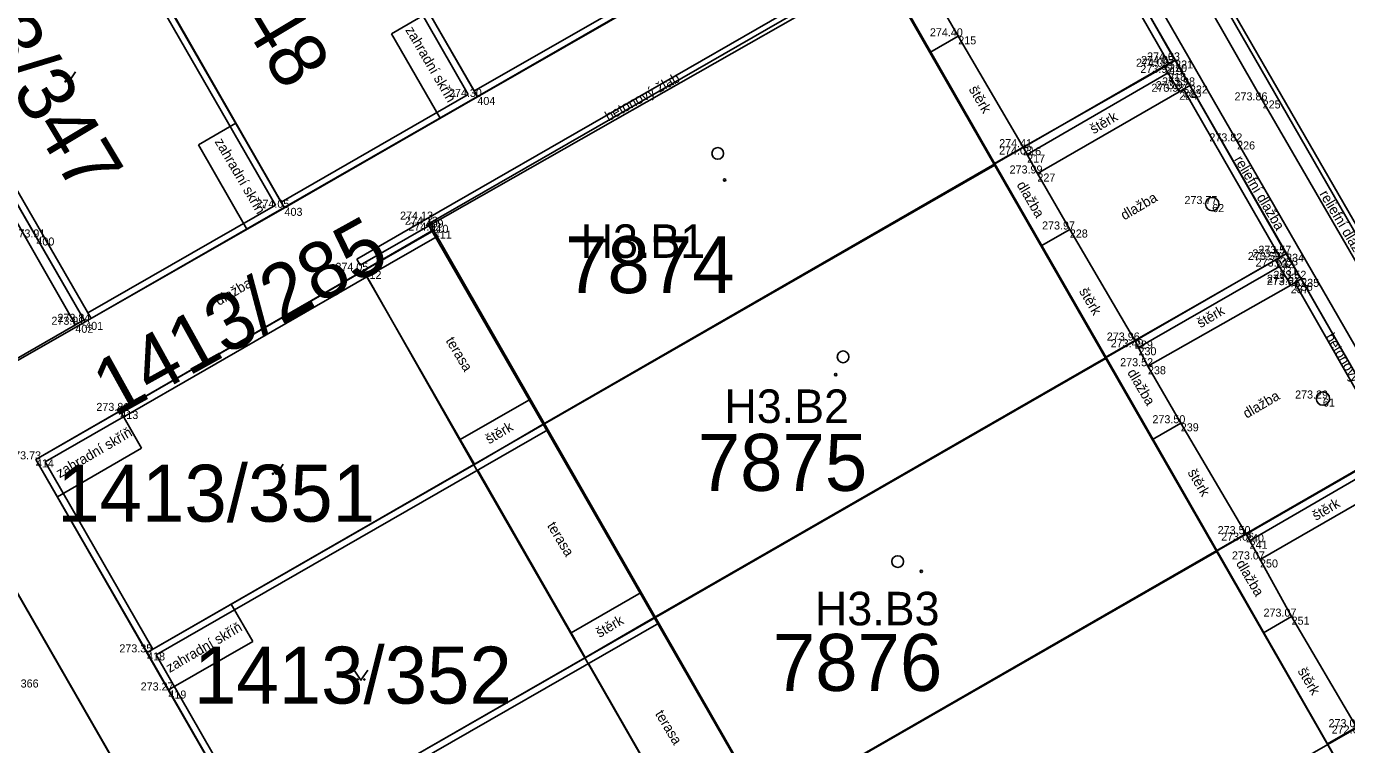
# Model space of a CAD drawing. Extents: x -771260 to -770828, y -1053564 to -1052811.
# Drawn here: x -770975.57 to -770936.17, y -1053197.5 to -1053176.07 of the extents above; entities that cross this region are included whole.
import ezdxf

# ---------------------------------------------------------------- set-up
doc = ezdxf.new("R2010")
doc.units = 0
for name, color, linetype in [('25_10_2019_asfalt', 7, 'Continuous'), ('25_10_2019_bet_zlab', 7, 'Continuous'), ('25_10_2019_budova', 7, 'Continuous'), ('25_10_2019_dlazba', 7, 'Continuous'), ('25_10_2019_operna_stena', 7, 'Continuous'), ('25_10_2019_popis_objektu', 7, 'Continuous'), ('25_10_2019_popis_povrchu', 7, 'Continuous'), ('25_10_2019_priska', 7, 'Continuous'), ('25_10_2019_reliefni_dlazba', 7, 'Continuous'), ('25_10_2019_sachta', 7, 'Continuous'), ('25_10_2019_sterk', 7, 'Continuous'), ('25_10_2019_terasa', 7, 'Continuous'), ('25_10_2019_zahradni_skrin', 7, 'Continuous'), ('25_10_2019_zamereny_bod', 7, 'Continuous'), ('25_10_2019_zamereny_bod_cislo', 7, 'Continuous'), ('25_10_2019_zamereny_bod_vyska', 7, 'Continuous'), ('25_10_2019_znacka_budovy', 7, 'Continuous'), ('25_10_2019_znacka_zelen', 7, 'Continuous'), ('Default', 7, 'Continuous'), ('DKM_Hranice parcel', 7, 'Continuous'), ('DKM_Parcelní čísla', 7, 'Continuous'), ('DKM_Vnitřní kresba', 7, 'Continuous'), ('DKM_Značky budov', 7, 'Continuous')]:
    doc.layers.add(name, color=color, linetype=linetype)

# ---------------------------------------------------------------- blocks, each defined once
blk = doc.blocks.new('6.200')
at = {"layer": '25_10_2019_sachta'}
blk.add_circle((0, 0), 10, dxfattribs=at)
blk = doc.blocks.new('4.020')
at = {"layer": '25_10_2019_znacka_budovy'}
blk.add_circle((0, 0), 1.75, dxfattribs=at)
blk = doc.blocks.new('3.140')
at = {"layer": '25_10_2019_znacka_zelen'}
blk.add_lwpolyline([(-10, 15), (0, 0), (10, 15)], dxfattribs=at)
for centre in [(-5, 1), (-5, 1), (5, 1), (5, 1)]:
    blk.add_circle(centre, 1, dxfattribs=at)
blk = doc.blocks.new('POINT_DISPLAY')
at = {"layer": 'Default'}
blk.add_line((0, 0), (0, 0), dxfattribs=at)

msp = doc.modelspace()

# ---------------------------------------------------------------- linework, layer by layer
at = {"layer": '25_10_2019_asfalt'}
msp.add_line((-770941.646, -1053172.006), (-770930.406, -1053191.509), dxfattribs=at)
at = {"layer": '25_10_2019_bet_zlab'}
for p, q in [((-770941.469, -1053177.19), (-770944.346, -1053172.178)), ((-770950.178, -1053174.073), (-770963.655, -1053181.835)), ((-770941.041, -1053177.943), (-770938.159, -1053182.962)), ((-770965.707, -1053183.016), (-770963.655, -1053181.835)), ((-770963.511, -1053181.988), (-770965.605, -1053183.194)), ((-770965.605, -1053183.194), (-770965.707, -1053183.016)), ((-770937.72, -1053183.717), (-770934.859, -1053188.733))]:
    msp.add_line(p, q, dxfattribs=at)
at = {"layer": '25_10_2019_budova'}
for p, q in [((-770963.511, -1053181.988), (-770950.052, -1053174.33)), ((-770950.052, -1053174.33), (-770930.001, -1053209.22)), ((-770960.104, -1053187.933), (-770946.672, -1053180.213)), ((-770943.484, -1053216.938), (-770963.511, -1053181.988)), ((-770956.797, -1053193.705), (-770943.356, -1053185.981)), ((-770953.496, -1053199.466), (-770940.048, -1053191.737))]:
    msp.add_line(p, q, dxfattribs=at)
at = {"layer": '25_10_2019_dlazba'}
for p, q in [((-770948.735, -1053174.674), (-770947.761, -1053176.364)), ((-770947.761, -1053176.364), (-770948.605, -1053176.849)), ((-770947.761, -1053176.364), (-770945.824, -1053179.672)), ((-770941.168, -1053178.018), (-770945.399, -1053180.458)), ((-770945.824, -1053179.672), (-770946.695, -1053180.173)), ((-770945.823, -1053179.672), (-770945.399, -1053180.458)), ((-770945.399, -1053180.458), (-770944.432, -1053182.129)), ((-770944.432, -1053182.129), (-770945.288, -1053182.621)), ((-770944.432, -1053182.129), (-770942.489, -1053185.443)), ((-770937.841, -1053183.79), (-770942.101, -1053186.21)), ((-770978.147, -1053187.297), (-770973.847, -1053184.824)), ((-770942.489, -1053185.443), (-770943.373, -1053185.951)), ((-770942.101, -1053186.21), (-770942.49, -1053185.444)), ((-770942.1, -1053186.209), (-770941.121, -1053187.912)), ((-770941.121, -1053187.912), (-770941.967, -1053188.398)), ((-770941.121, -1053187.912), (-770939.175, -1053191.221)), ((-770934.528, -1053189.544), (-770938.757, -1053191.977)), ((-770977.395, -1053190.28), (-770957.487, -1053224.903)), ((-770939.175, -1053191.221), (-770940.054, -1053191.727)), ((-770939.175, -1053191.221), (-770937.814, -1053193.683)), ((-770937.814, -1053193.683), (-770938.653, -1053194.165)), ((-770937.814, -1053193.683), (-770935.873, -1053196.983)), ((-770935.873, -1053196.983), (-770936.745, -1053197.484))]:
    msp.add_line(p, q, dxfattribs=at)
at = {"layer": '25_10_2019_operna_stena'}
for p, q in [((-770962.383, -1053178.099), (-770970.556, -1053163.861)), ((-770962.111, -1053178.173), (-770970.382, -1053163.761)), ((-770968.137, -1053181.407), (-770976.311, -1053167.164)), ((-770967.863, -1053181.482), (-770976.138, -1053167.065)), ((-770980.916, -1053172.597), (-770973.811, -1053184.886)), ((-770980.743, -1053172.497), (-770973.638, -1053184.785)), ((-770962.211, -1053177.999), (-770956.626, -1053174.798)), ((-770962.111, -1053178.173), (-770956.352, -1053174.872)), ((-770941.608, -1053177.272), (-770945.824, -1053179.672)), ((-770945.705, -1053179.891), (-770941.499, -1053177.456)), ((-770967.962, -1053181.309), (-770962.383, -1053178.099)), ((-770967.863, -1053181.482), (-770962.111, -1053178.173)), ((-770973.811, -1053184.886), (-770967.863, -1053181.482)), ((-770973.737, -1053184.613), (-770968.137, -1053181.407)), ((-770965.507, -1053183.363), (-770963.411, -1053182.162)), ((-770965.408, -1053183.537), (-770963.312, -1053182.336)), ((-770965.507, -1053183.363), (-770972.763, -1053187.543)), ((-770942.489, -1053185.443), (-770938.289, -1053183.039)), ((-770938.173, -1053183.235), (-770942.383, -1053185.655)), ((-770965.407, -1053183.537), (-770972.663, -1053187.716)), ((-770972.763, -1053187.543), (-770975.283, -1053188.99)), ((-770972.664, -1053187.716), (-770975.009, -1053189.063)), ((-770971.964, -1053194.75), (-770960.104, -1053187.933)), ((-770971.697, -1053194.827), (-770960.005, -1053188.107)), ((-770934.972, -1053188.8), (-770939.175, -1053191.221)), ((-770975.283, -1053188.99), (-770955.348, -1053223.679)), ((-770975.009, -1053189.063), (-770971.797, -1053194.654)), ((-770939.067, -1053191.417), (-770934.865, -1053188.979)), ((-770968.662, -1053200.513), (-770956.797, -1053193.705)), ((-770968.388, -1053200.586), (-770956.697, -1053193.879)), ((-770971.697, -1053194.827), (-770968.487, -1053200.413))]:
    msp.add_line(p, q, dxfattribs=at)
at = {"layer": '25_10_2019_priska'}
for p, q in [((-770941.289, -1053177.084), (-770941.608, -1053177.272)), ((-770941.168, -1053178.018), (-770941.608, -1053177.272)), ((-770941.289, -1053177.084), (-770940.849, -1053177.83)), ((-770941.168, -1053178.018), (-770940.849, -1053177.83)), ((-770937.978, -1053182.853), (-770938.29, -1053183.04)), ((-770937.978, -1053182.853), (-770937.528, -1053183.602)), ((-770937.841, -1053183.79), (-770938.29, -1053183.04)), ((-770937.528, -1053183.602), (-770937.841, -1053183.79))]:
    msp.add_line(p, q, dxfattribs=at)
at = {"layer": '25_10_2019_reliefni_dlazba'}
for p, q in [((-770938.678, -1053178.275), (-770944.533, -1053168.051)), ((-770945.645, -1053168.702), (-770939.439, -1053179.5)), ((-770944.15, -1053172.053), (-770941.295, -1053177.073)), ((-770940.849, -1053177.83), (-770937.978, -1053182.853)), ((-770932.298, -1053189.326), (-770938.678, -1053178.275)), ((-770939.439, -1053179.5), (-770933.337, -1053190.101)), ((-770937.528, -1053183.602), (-770934.661, -1053188.616))]:
    msp.add_line(p, q, dxfattribs=at)
at = {"layer": '25_10_2019_sterk'}
for p, q in [((-770982.74, -1053169.889), (-770974.104, -1053184.972)), ((-770962.197, -1053189.136), (-770962.621, -1053188.397)), ((-770958.889, -1053194.905), (-770959.313, -1053194.166))]:
    msp.add_line(p, q, dxfattribs=at)
at = {"layer": '25_10_2019_terasa'}
for p, q in [((-770962.621, -1053188.397), (-770965.407, -1053183.537)), ((-770962.621, -1053188.397), (-770960.576, -1053187.22)), ((-770959.313, -1053194.166), (-770962.097, -1053189.309)), ((-770959.313, -1053194.166), (-770957.222, -1053192.963)), ((-770956.005, -1053199.934), (-770958.789, -1053195.079))]:
    msp.add_line(p, q, dxfattribs=at)
at = {"layer": '25_10_2019_zahradni_skrin'}
for p, q in [((-770964.671, -1053176.285), (-770963.556, -1053175.645)), ((-770963.218, -1053178.81), (-770964.671, -1053176.285)), ((-770970.435, -1053179.602), (-770969.313, -1053178.956)), ((-770968.984, -1053182.123), (-770970.435, -1053179.602)), ((-770972.128, -1053188.658), (-770972.768, -1053187.546)), ((-770974.642, -1053190.105), (-770972.128, -1053188.658)), ((-770968.812, -1053194.422), (-770969.454, -1053193.307)), ((-770971.329, -1053195.87), (-770968.812, -1053194.422))]:
    msp.add_line(p, q, dxfattribs=at)
at = {"layer": 'DKM_Hranice parcel'}
for p, q in [((-770962.11, -1053178.16), (-770969.19, -1053165.87)), ((-770967.87, -1053181.47), (-770974.95, -1053169.18)), ((-770980.91, -1053172.6), (-770973.81, -1053184.88)), ((-770956.36, -1053174.85), (-770962.11, -1053178.16)), ((-770941.29, -1053177.07), (-770937.97, -1053182.85)), ((-770962.11, -1053178.16), (-770967.87, -1053181.47)), ((-770967.87, -1053181.47), (-770973.81, -1053184.88)), ((-770937.97, -1053182.85), (-770934.66, -1053188.61)), ((-770965.51, -1053183.35), (-770962.22, -1053189.15)), ((-770973.81, -1053184.88), (-770986.09, -1053191.86)), ((-770971.96, -1053194.75), (-770962.22, -1053189.15)), ((-770962.22, -1053189.15), (-770958.9, -1053194.91)), ((-770968.66, -1053200.51), (-770971.96, -1053194.75)), ((-770968.66, -1053200.51), (-770958.9, -1053194.91)), ((-770958.9, -1053194.91), (-770955.59, -1053200.67))]:
    msp.add_line(p, q, dxfattribs=at)
for points in [[(-770947.48, -1053162.13), (-770920.03, -1053209.83), (-770918.34, -1053212.34), (-770918.21, -1053212.26), (-770916, -1053215.59)], [(-770965.51, -1053183.35), (-770963.47, -1053182.17), (-770963.59, -1053181.97), (-770950.09, -1053174.2), (-770949.97, -1053174.41), (-770944.61, -1053171.31), (-770941.29, -1053177.07)], [(-770962.22, -1053189.15), (-770960.15, -1053187.94), (-770946.67, -1053180.17), (-770941.29, -1053177.07)], [(-770958.9, -1053194.91), (-770956.83, -1053193.71), (-770943.35, -1053185.95), (-770937.97, -1053182.85)], [(-770971.96, -1053194.75), (-770975.28, -1053188.99), (-770965.51, -1053183.35)], [(-770955.59, -1053200.67), (-770953.52, -1053199.47), (-770940.05, -1053191.71), (-770934.66, -1053188.61)], [(-770984.27, -1053194.26), (-770977.39, -1053190.28), (-770957.49, -1053224.9), (-770960.18, -1053226.44)], [(-770952.28, -1053206.45), (-770950.2, -1053205.25), (-770936.73, -1053197.5), (-770931.33, -1053194.39)]]:
    msp.add_lwpolyline(points, dxfattribs=at)
at = {"layer": 'DKM_Vnitřní kresba'}
for p, q in [((-770946.67, -1053180.17), (-770949.97, -1053174.41)), ((-770943.35, -1053185.95), (-770946.67, -1053180.17)), ((-770963.47, -1053182.17), (-770960.15, -1053187.94)), ((-770940.05, -1053191.71), (-770943.35, -1053185.95)), ((-770960.15, -1053187.94), (-770956.83, -1053193.71)), ((-770936.73, -1053197.5), (-770940.05, -1053191.71)), ((-770956.83, -1053193.71), (-770953.52, -1053199.47)), ((-770933.42, -1053203.26), (-770936.73, -1053197.5))]:
    msp.add_line(p, q, dxfattribs=at)
at = {"layer": 'DKM_Značky budov'}
for centre in [(-770954.937, -1053179.859), (-770951.197, -1053185.929), (-770949.567, -1053192.039)]:
    msp.add_circle(centre, 0.175, dxfattribs=at)

# ---------------------------------------------------------------- block references
at = {"layer": '25_10_2019_sachta', "xscale": 0.020000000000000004, "yscale": 0.020000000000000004}
for p in [(-770940.184, -1053181.37), (-770936.881, -1053187.174)]:
    msp.add_blockref('6.200', p, dxfattribs=at)
at = {"layer": '25_10_2019_zamereny_bod', "xscale": 0.1, "yscale": 0.10000000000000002}
for p in [(-770947.761, -1053176.364), (-770941.608, -1053177.272), (-770941.499, -1053177.456), (-770941.469, -1053177.19), (-770941.289, -1053177.084), (-770940.849, -1053177.83), (-770962.111, -1053178.173), (-770941.168, -1053178.018), (-770941.041, -1053177.943), (-770938.678, -1053178.276), (-770945.824, -1053179.672), (-770939.44, -1053179.5), (-770945.705, -1053179.891), (-770945.399, -1053180.458), (-770940.184, -1053181.37), (-770967.864, -1053181.482), (-770963.656, -1053181.835), (-770963.511, -1053181.988), (-770963.411, -1053182.162), (-770944.432, -1053182.129), (-770975.268, -1053182.367), (-770938.159, -1053182.962), (-770937.978, -1053182.853), (-770965.507, -1053183.363), (-770938.29, -1053183.04), (-770938.173, -1053183.235), (-770937.72, -1053183.717), (-770937.528, -1053183.602), (-770937.841, -1053183.79), (-770973.812, -1053184.886), (-770974.105, -1053184.973), (-770942.49, -1053185.444), (-770942.383, -1053185.643), (-770942.101, -1053186.21), (-770936.881, -1053187.174), (-770972.764, -1053187.544), (-770941.121, -1053187.912), (-770975.283, -1053188.99), (-770939.175, -1053191.222), (-770939.067, -1053191.417), (-770938.757, -1053191.977), (-770937.815, -1053193.684), (-770971.965, -1053194.751), (-770971.33, -1053195.888)]:
    msp.add_blockref('POINT_DISPLAY', p, dxfattribs=at)
at = {"layer": '25_10_2019_znacka_budovy', "xscale": 0.020000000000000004, "yscale": 0.020000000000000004}
for p in [(-770954.733, -1053180.65), (-770951.416, -1053186.459), (-770948.863, -1053192.333)]:
    msp.add_blockref('4.020', p, dxfattribs=at)
at = {"layer": '25_10_2019_znacka_zelen', "xscale": 0.020000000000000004, "yscale": 0.020000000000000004}
for p in [(-770974.3, -1053177.727), (-770968.104, -1053189.437), (-770965.583, -1053195.58)]:
    msp.add_blockref('3.140', p, dxfattribs=at)

# ---------------------------------------------------------------- texts
at = {"layer": '25_10_2019_popis_objektu'}
for s, rotation, p in [('zahradní skříň', 300.3604, (-770964.269, -1053176.172)), ('zahradní skříň', 300.3604, (-770969.959, -1053179.504)), ('terasa', 301.0481, (-770963.066, -1053185.445)), ('zahradní skříň', 30.3604, (-770974.573, -1053189.556)), ('terasa', 301.0481, (-770960.039, -1053190.965)), ('zahradní skříň', 30.3604, (-770971.293, -1053195.368)), ('terasa', 301.0481, (-770956.817, -1053196.583))]:
    msp.add_text(s, height=0.3, rotation=rotation, dxfattribs=at).set_placement(p)
for s, p in [('H3.B1', (-770959.027, -1053182.976)), ('H3.B2', (-770954.738, -1053187.903)), ('H3.B3', (-770952.037, -1053193.943))]:
    msp.add_text(s, height=1, dxfattribs=at).set_placement(p)
at = {"layer": '25_10_2019_popis_povrchu'}
for s, rotation, p in [('betonový žlab', 29.3966, (-770958.195, -1053178.91)), ('štěrk', 300.687, (-770947.457, -1053177.945)), ('štěrk', 30.687, (-770943.722, -1053179.291)), ('reliefní dlažba', 300.687, (-770939.538, -1053180.037)), ('dlažba', 300.687, (-770946.03, -1053180.795)), ('reliefní dlažba', 300.687, (-770936.994, -1053181.067)), ('dlažba', 30.687, (-770942.805, -1053181.862)), ('dlažba', 30.687, (-770969.822, -1053184.413)), ('štěrk', 300.687, (-770944.167, -1053183.97)), ('štěrk', 30.687, (-770940.531, -1053185.077)), ('betonový žlab', 300.687, (-770936.82, -1053185.331)), ('dlažba', 300.687, (-770942.728, -1053186.397)), ('dlažba', 30.687, (-770939.154, -1053187.78)), ('štěrk', 30.687, (-770961.761, -1053188.546)), ('štěrk', 300.687, (-770940.929, -1053189.38)), ('štěrk', 30.687, (-770937.088, -1053190.828)), ('dlažba', 300.687, (-770939.482, -1053192.094)), ('štěrk', 30.687, (-770958.463, -1053194.321)), ('štěrk', 300.687, (-770937.645, -1053195.305))]:
    msp.add_text(s, height=0.3, rotation=rotation, dxfattribs=at).set_placement(p)
at = {"layer": '25_10_2019_zamereny_bod_cislo'}
for s, p in [('215', (-770947.761, -1053176.604)), ('219', (-770941.608, -1053177.512)), ('218', (-770941.499, -1053177.696)), ('220', (-770941.469, -1053177.43)), ('221', (-770941.289, -1053177.324)), ('222', (-770940.849, -1053178.07)), ('404', (-770962.111, -1053178.413)), ('224', (-770941.168, -1053178.258)), ('223', (-770941.041, -1053178.183)), ('225', (-770938.678, -1053178.516)), ('216', (-770945.824, -1053179.912)), ('226', (-770939.44, -1053179.74)), ('217', (-770945.705, -1053180.131)), ('227', (-770945.399, -1053180.698)), ('62', (-770940.184, -1053181.61)), ('403', (-770967.864, -1053181.722)), ('409', (-770963.656, -1053182.075)), ('410', (-770963.511, -1053182.228)), ('411', (-770963.411, -1053182.402)), ('228', (-770944.432, -1053182.369)), ('400', (-770975.268, -1053182.607)), ('233', (-770938.159, -1053183.202)), ('234', (-770937.978, -1053183.093)), ('412', (-770965.507, -1053183.603)), ('232', (-770938.29, -1053183.28)), ('231', (-770938.173, -1053183.475)), ('236', (-770937.72, -1053183.957)), ('235', (-770937.528, -1053183.842)), ('237', (-770937.841, -1053184.03)), ('401', (-770973.812, -1053185.126)), ('402', (-770974.105, -1053185.213)), ('229', (-770942.49, -1053185.684)), ('230', (-770942.383, -1053185.883)), ('238', (-770942.101, -1053186.45)), ('61', (-770936.881, -1053187.414)), ('413', (-770972.764, -1053187.784)), ('239', (-770941.121, -1053188.152)), ('414', (-770975.283, -1053189.23)), ('240', (-770939.175, -1053191.462)), ('241', (-770939.067, -1053191.657)), ('250', (-770938.757, -1053192.217)), ('251', (-770937.815, -1053193.924)), ('418', (-770971.965, -1053194.991)), ('366', (-770975.738, -1053195.799)), ('419', (-770971.33, -1053196.128))]:
    msp.add_text(s, height=0.24, dxfattribs=at).set_placement(p)
at = {"layer": '25_10_2019_zamereny_bod_vyska'}
for s, p in [('274.40 ', (-770948.607, -1053176.364)), ('274.06 ', (-770942.457, -1053177.272)), ('274.05 ', (-770942.307, -1053177.19)), ('274.03 ', (-770942.127, -1053177.084)), ('273.97 ', (-770942.327, -1053177.456)), ('273.98 ', (-770941.997, -1053178.018)), ('273.97 ', (-770941.869, -1053177.943)), ('273.98 ', (-770941.678, -1053177.83)), ('274.30 ', (-770962.957, -1053178.173)), ('273.86 ', (-770939.517, -1053178.276)), ('273.82 ', (-770940.268, -1053179.5)), ('274.03 ', (-770946.543, -1053179.891)), ('274.41 ', (-770946.539, -1053179.672)), ('273.99 ', (-770946.229, -1053180.458)), ('274.05 ', (-770968.702, -1053181.482)), ('273.77 ', (-770941.011, -1053181.37)), ('274.13 ', (-770964.416, -1053181.835)), ('274.12 ', (-770964.271, -1053181.988)), ('273.91 ', (-770975.983, -1053182.367)), ('274.12 ', (-770964.171, -1053182.162)), ('273.97 ', (-770945.26, -1053182.129)), ('273.59 ', (-770939.119, -1053183.04)), ('273.57 ', (-770938.986, -1053182.962)), ('273.57 ', (-770938.805, -1053182.853)), ('274.05 ', (-770966.345, -1053183.363)), ('273.51 ', (-770938.888, -1053183.235)), ('273.52 ', (-770938.356, -1053183.602)), ('273.51 ', (-770938.556, -1053183.79)), ('273.52 ', (-770938.548, -1053183.717)), ('273.91 ', (-770974.82, -1053184.973)), ('273.84 ', (-770974.64, -1053184.886)), ('273.96 ', (-770943.329, -1053185.444)), ('273.49 ', (-770943.212, -1053185.643)), ('273.52 ', (-770942.929, -1053186.21)), ('273.81 ', (-770973.479, -1053187.544)), ('273.29 ', (-770937.71, -1053187.174)), ('273.50 ', (-770941.967, -1053187.912)), ('273.73 ', (-770976.111, -1053188.99)), ('273.50 ', (-770940.021, -1053191.222)), ('273.06 ', (-770939.916, -1053191.417)), ('273.07 ', (-770939.594, -1053191.977)), ('273.07 ', (-770938.652, -1053193.684)), ('273.35 ', (-770972.793, -1053194.751)), ('273.27 ', (-770972.157, -1053195.888)), ('273.05 ', (-770936.712, -1053196.983)), ('272.60 ', (-770936.619, -1053197.173))]:
    msp.add_text(s, height=0.24, dxfattribs=at).set_placement(p)
at = {"layer": 'DKM_Parcelní čísla'}
for s, rotation, p in [('1413/348', 301, (-770972.76, -1053169.921)), ('1413/347', 301, (-770978.95, -1053173.091)), ('1413/285', 29, (-770972.946, -1053187.746))]:
    msp.add_text(s, height=1.7, rotation=rotation, dxfattribs=at).set_placement(p)
for s, p in [('7874', (-770959.494, -1053184.029)), ('7875', (-770955.534, -1053189.93)), ('1413/351', (-770974.645, -1053190.85)), ('7876', (-770953.294, -1053195.9)), ('1413/352', (-770970.565, -1053196.279))]:
    msp.add_text(s, height=1.7, dxfattribs=at).set_placement(p)

doc.saveas('drawing.dxf')
